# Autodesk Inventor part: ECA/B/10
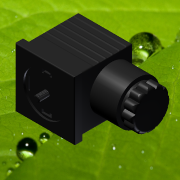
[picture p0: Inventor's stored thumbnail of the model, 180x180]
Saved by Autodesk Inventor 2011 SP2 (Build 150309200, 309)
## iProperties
Category: PARTsolutions
Created: 2013-04
Part Number: ECA/B/10
Catalog Web Link: www.cadenas.de
Description: EC - Electric connectors
Document SubType Name: Modeling
Designer: PARTsolutions
Material: Пластмасса ABS
Mass: 32.0166 g
Surface Area: 73.2471 cm^2
Volume: 30.2044 cm^3
Density: 1.06 g/cm^3
NB: ECA/B/10
NN: EC
NT: Electric connectors
NBSYN: $TIPO.$CT./$CO./$SR.
LINA: ECA/B/10
TIPO: EC
CT: A
CO: B
SR: 10
COX: 'B','B = black','A','A = grey'
VER: 1
KT: DUMMY
CreationOption_UseAsmMates: false
SUPPLIER: Duplomatic
ARTICLENO: ECA/B/10
BOMINFO: ECA/B/10
CREATOR: CADENAS GmbH
PSOL_IDENT_0: {$CADENAS_DATA\23d-libs\duplomatic\04_solenoid_operated_valves\49000\ec.prj},159 {VTYP=3D},{NB=ECA/B
PSOL_IDENT_1: /10},{LINA=ECA/B/10},{NN=EC},{DATE=03.08.2011 09:28:10},{GEOMDATE=03.08.2011 00:00:00},{VERSION=},{L
PSOL_IDENT_2: INEID=10},{LINESUBID=-1},{WBVAR=CT,CO}  {NB=ECA/B/10},{LINA=ECA/B/10},{KT=DUMMY},{TIPO=EC},{CT=A},{C
PSOL_IDENT_3: O=B},{SR=10},{COX= 'B','B = black','A','A = grey' },{VER=1}
Title: ECA/B/10
Author: Cadenas PARTsolutions
Comments: Electric connectors
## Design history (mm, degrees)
sketch "Sketch_3"
  geometry: L1 (11.5, 13.5)-(-11.5, 13.5); L2 (-13.5, 11.5)-(-13.5, -11.5); L3 (-11.5, -13.5)-(11.5, -13.5); L4 (13.5, -11.5)-(13.5, 11.5); A1 r 2 centre (11.5, 11.5) between (13.5, 11.5) and (11.5, 13.5); A2 r 2 centre (-11.5, 11.5) between (-11.5, 13.5) and (-13.5, 11.5); A3 r 2 centre (-11.5, -11.5) between (-13.5, -11.5) and (-11.5, -13.5); A4 r 2 centre (11.5, -11.5) between (11.5, -13.5) and (13.5, -11.5)
  constraints: 8 end point, 8 point on circle, 4 centre point
extrude "Extrusion1" join sketch "Sketch_3" distance "d0" = 4.99; taper "d1" = 0 deg
sketch "Sketch_5"
  geometry: L1 (-13.05, -13.75)-(13.05, -13.75); L2 (13.75, -13.05)-(13.75, 13.05); L3 (13.05, 13.75)-(-13.05, 13.75); L4 (-13.75, 13.05)-(-13.75, -13.05); A1 r 0.7 centre (-13.05, -13.05) between (-13.75, -13.05) and (-13.05, -13.75); A2 r 0.7 centre (13.05, -13.05) between (13.05, -13.75) and (13.75, -13.05); A3 r 0.7 centre (13.05, 13.05) between (13.75, 13.05) and (13.05, 13.75); A4 r 0.7 centre (-13.05, 13.05) between (-13.05, 13.75) and (-13.75, 13.05)
  constraints: 8 end point, 8 point on circle, 4 centre point
extrude "Extrusion2" join sketch "Sketch_5" distance "d2" = 30; taper "d3" = 0 deg
sketch "Sketch_32"
  geometry: L1 (-18.75, 32)-(-18.75, 17); L2 (-18.75, 17)-(-13.75, 17); L3 (-13.75, 17)-(-13.75, 26); L4 (-12.75, 27)-(12.75, 27); L5 (13.75, 26)-(13.75, 17); L6 (13.75, 17)-(18.75, 17); L7 (18.75, 17)-(18.75, 32); L8 (18.75, 32)-(-18.75, 32); A1 r 1 centre (-12.75, 26) between (-12.75, 27) and (-13.75, 26); A2 r 1 centre (12.75, 26) between (13.75, 26) and (12.75, 27)
  constraints: 16 end point, 4 point on circle, 2 centre point
extrude "Extrusion3" cut sketch "Sketch_32" stored distance "d4" = 60; taper "d5" = 0 deg
sketch "Sketch_33"
  geometry: L1 (32, 18.75)-(17, 18.75); L2 (17, 18.75)-(17, 13.75); L3 (17, 13.75)-(26, 13.75); L4 (27, 12.75)-(27, -12.75); L5 (26, -13.75)-(17, -13.75); L6 (17, -13.75)-(17, -18.75); L7 (17, -18.75)-(32, -18.75); L8 (32, -18.75)-(32, 18.75); A1 r 1 centre (26, 12.75) between (27, 12.75) and (26, 13.75); A2 r 1 centre (26, -12.75) between (26, -13.75) and (27, -12.75)
  constraints: 16 end point, 4 point on circle, 2 centre point
extrude "Extrusion4" cut sketch "Sketch_33" stored distance "d6" = 60; taper "d7" = 0 deg
sketch "Sketch_1"
  geometry: L1 (27.25, 16)-(0, 16); L2 (0, 16)-(0, 27); L3 (0, 27)-(27.25, 27); L4 (27.25, 27)-(27.25, 16); L5 (27.25, 16)-(0, 16)
  constraints: 10 end point
revolve "Revolution1" sketch "Sketch_1" stored, may be unused: angle "d8" = 360 deg
sketch "Sketch_2"
  geometry: L1 (34.16, 16)-(27.25, 16); L2 (27.25, 16)-(27.25, 24.95); L3 (27.25, 24.95)-(28.85, 24.95); L4 (28.85, 24.95)-(28.85, 25.95); L5 (28.85, 25.95)-(32.41, 25.95); L6 (34.16, 24.2)-(34.16, 16); L7 (34.16, 16)-(27.25, 16); A1 r 1.75 centre (32.41, 24.2) between (34.16, 24.2) and (32.41, 25.95)
  constraints: 14 end point, 2 point on circle, 1 centre point
revolve "Revolution2" sketch "Sketch_2" stored, may be unused: angle "d9" = 360 deg
sketch "Sketch_4"
  geometry: L1 (-15, 30)-(-15, 0); L2 (-15, 0)-(15, 0); L3 (15, 0)-(15, 30); L4 (15, 30)-(-15, 30); L5 (-8.95, 14.268)-(-8.162, 13.813); L6 (-8.162, 13.813)-(-8.617, 13.025); L7 (-6.885, 10.025)-(-5.975, 10.025); L8 (-5.975, 10.025)-(-5.975, 9.115); L9 (-2.975, 7.383)-(-2.187, 7.838); L10 (-2.187, 7.838)-(-1.732, 7.05); L11 (1.732, 7.05)-(2.187, 7.838); L12 (2.187, 7.838)-(2.975, 7.383); L13 (5.975, 9.115)-(5.975, 10.025); L14 (5.975, 10.025)-(6.885, 10.025); L15 (8.617, 13.025)-(8.162, 13.813); L16 (8.162, 13.813)-(8.95, 14.268); L17 (8.95, 17.732)-(8.162, 18.187); L18 (8.162, 18.187)-(8.617, 18.975); L19 (6.885, 21.975)-(5.975, 21.975); L20 (5.975, 21.975)-(5.975, 22.885); L21 (2.975, 24.617)-(2.187, 24.162); L22 (2.187, 24.162)-(1.732, 24.95); L23 (-1.732, 24.95)-(-2.187, 24.162); L24 (-2.187, 24.162)-(-2.975, 24.617); L25 (-5.975, 22.885)-(-5.975, 21.975); L26 (-5.975, 21.975)-(-6.885, 21.975); L27 (-8.617, 18.975)-(-8.162, 18.187); L28 (-8.162, 18.187)-(-8.95, 17.732); A1 r 2 centre (-7.95, 16) between (-8.95, 17.732) and (-8.95, 14.268); A2 r 2 centre (-6.885, 12.025) between (-8.617, 13.025) and (-6.885, 10.025); A3 r 2 centre (-3.975, 9.115) between (-5.975, 9.115) and (-2.975, 7.383); A4 r 2 centre (0, 8.05) between (-1.732, 7.05) and (1.732, 7.05); A5 r 2 centre (3.975, 9.115) between (2.975, 7.383) and (5.975, 9.115); A6 r 2 centre (6.885, 12.025) between (6.885, 10.025) and (8.617, 13.025); A7 r 2 centre (7.95, 16) between (8.95, 14.268) and (8.95, 17.732); A8 r 2 centre (6.885, 19.975) between (8.617, 18.975) and (6.885, 21.975); A9 r 2 centre (3.975, 22.885) between (5.975, 22.885) and (2.975, 24.617); A10 r 2 centre (0, 23.95) between (1.732, 24.95) and (-1.732, 24.95); A11 r 2 centre (-3.975, 22.885) between (-2.975, 24.617) and (-5.975, 22.885); A12 r 2 centre (-6.885, 19.975) between (-6.885, 21.975) and (-8.617, 18.975)
  constraints: 56 end point, 24 point on circle, 12 centre point
extrude "Extrusion5" cut sketch "Sketch_4" distance "d10" = 10; taper "d11" = 0 deg
sketch "Sketch_6"
  geometry: L1 (0, -8.3)-(0, -2); L2 (0, -2)-(1.5, -2); L3 (1.5, -2)-(1.5, -7.994); L4 (1.5, -7.994)-(1.194, -8.3); L5 (1.194, -8.3)-(0, -8.3); L6 (0, -8.3)-(0, -2)
  constraints: 12 end point
revolve "Revolution3" sketch "Sketch_6" stored, may be unused: angle "d12" = 360 deg
thread "Thread1" dims "d13" = 6.3, "d14" = 0
sketch "Sketch_7"
  geometry: C1 r 3.15 at (0, 0); 1 further point
  constraints: 1 centre point
extrude "Extrusion6" cut sketch "Sketch_7" distance "d15" = 4; taper "d16" = 0 deg
sketch "Sketch_8"
  geometry: L1 (0, 23.5)-(0, 26); L2 (0, 26)-(1, 26); L3 (2.5, 24.5)-(2.5, 23.987); L4 (2.5, 23.987)-(3, 23.987); L5 (3, 23.987)-(3, 23.5); L6 (3, 23.5)-(0, 23.5); L7 (0, 23.5)-(0, 26); A1 r 1.5 centre (1, 24.5) between (2.5, 24.5) and (1, 26)
  constraints: 14 end point, 2 point on circle, 1 centre point
revolve "Revolution4" sketch "Sketch_8" stored, may be unused: angle "d17" = 360 deg
sketch "Sketch_9"
  geometry: L1 (-1.5, 0.3)-(-1.5, -0.3); L2 (-1.5, -0.3)-(-0.3, -0.3); L3 (-0.3, -0.3)-(-0.3, -1.5); L4 (-0.3, -1.5)-(0.3, -1.5); L5 (0.3, -1.5)-(0.3, -0.3); L6 (0.3, -0.3)-(1.5, -0.3); L7 (1.5, -0.3)-(1.5, 0.3); L8 (1.5, 0.3)-(0.3, 0.3); L9 (0.3, 0.3)-(0.3, 1.5); L10 (0.3, 1.5)-(-0.3, 1.5); L11 (-0.3, 1.5)-(-0.3, 0.3); L12 (-0.3, 0.3)-(-1.5, 0.3)
  constraints: 24 end point
extrude "Extrusion7" cut sketch "Sketch_9" distance "d18" = 2; taper "d19" = 0 deg
sketch "Sketch_10"
  geometry: L1 (-9.3, 3.25)-(-9.3, -3.25); L2 (-9.3, -3.25)-(-8.5, -3.25); L3 (-8.5, -3.25)-(-8.5, 3.25); L4 (-8.5, 3.25)-(-9.3, 3.25)
  constraints: 8 end point
extrude "Extrusion8" cut sketch "Sketch_10" distance "d20" = 12; taper "d21" = 0 deg
sketch "Sketch_11"
  geometry: L1 (-2.5, 9.8)-(-2.5, 7.9); L2 (-2.5, 7.9)-(-1.5, 7.9); L3 (-1.5, 7.9)-(-1.5, 8.8); L4 (-1.5, 8.8)-(1.5, 8.8); L5 (1.5, 8.8)-(1.5, 7.9); L6 (1.5, 7.9)-(2.5, 7.9); L7 (2.5, 7.9)-(2.5, 9.8); L8 (2.5, 9.8)-(-2.5, 9.8)
  constraints: 16 end point
extrude "Extrusion9" cut sketch "Sketch_11" distance "d22" = 10; taper "d23" = 0 deg
sketch "Sketch_12"
  geometry: L1 (-2.5, -9.8)-(2.5, -9.8); L2 (2.5, -9.8)-(2.5, -7.9); L3 (2.5, -7.9)-(1.5, -7.9); L4 (1.5, -7.9)-(1.5, -8.8); L5 (1.5, -8.8)-(-1.5, -8.8); L6 (-1.5, -8.8)-(-1.5, -7.9); L7 (-1.5, -7.9)-(-2.5, -7.9); L8 (-2.5, -7.9)-(-2.5, -9.8)
  constraints: 16 end point
extrude "Extrusion10" cut sketch "Sketch_12" distance "d24" = 10; taper "d25" = 0 deg
sketch "Sketch_14"
  geometry: L1 (15, -15)-(15, 15); L2 (15, 15)-(-15, 15); L3 (-15, 15)-(-15, -15); L4 (-15, -15)-(15, -15); C1 r 10.9 at (0, 0); 1 further point
  constraints: 8 end point, 1 centre point
extrude "Extrusion11" join sketch "Sketch_14" distance "d26" = 4; taper "d27" = 0 deg
sketch "Sketch_30"
  geometry: L1 (-20, 0)-(-20, -14); L2 (-20, -14)-(20, -14); L3 (20, -14)-(20, 0); L4 (20, 0)-(15, 0); L5 (15, 0)-(15, -3.5); L6 (14.5, -4)-(10, -4); L7 (10, -4)-(10, -9); L8 (10, -9)-(-10, -9); L9 (-10, -9)-(-10, -4); L10 (-10, -4)-(-14.5, -4); L11 (-15, -3.5)-(-15, 0); L12 (-15, 0)-(-20, 0); A1 r 0.5 centre (14.5, -3.5) between (14.5, -4) and (15, -3.5); A2 r 0.5 centre (-14.5, -3.5) between (-15, -3.5) and (-14.5, -4)
  constraints: 24 end point, 4 point on circle, 2 centre point
extrude "Extrusion12" cut sketch "Sketch_30" stored distance "d28" = 60; taper "d29" = 0 deg
sketch "Sketch_31"
  geometry: L1 (0, 20)-(-14, 20); L2 (-14, 20)-(-14, -20); L3 (-14, -20)-(0, -20); L4 (0, -20)-(0, -15); L5 (0, -15)-(-3.5, -15); L6 (-4, -14.5)-(-4, -10); L7 (-4, -10)-(-9, -10); L8 (-9, -10)-(-9, 10); L9 (-9, 10)-(-4, 10); L10 (-4, 10)-(-4, 14.5); L11 (-3.5, 15)-(0, 15); L12 (0, 15)-(0, 20); A1 r 0.5 centre (-3.5, -14.5) between (-4, -14.5) and (-3.5, -15); A2 r 0.5 centre (-3.5, 14.5) between (-3.5, 15) and (-4, 14.5)
  constraints: 24 end point, 4 point on circle, 2 centre point
extrude "Extrusion13" cut sketch "Sketch_31" stored distance "d30" = 60; taper "d31" = 0 deg
sketch "Sketch_16"
  geometry: L1 (6.7, 15)-(6.7, 13.75); L2 (6.7, 13.75)-(7.249, 13.55); L3 (7.249, 13.55)-(9.611, 13.55); L4 (9.611, 13.55)-(10.16, 13.75); L5 (10.16, 13.75)-(10.2, 13.75); L6 (10.2, 13.75)-(10.749, 13.55); L7 (10.749, 13.55)-(13.111, 13.55); L8 (13.111, 13.55)-(13.66, 13.75); L9 (13.66, 13.75)-(13.7, 13.75); L10 (13.7, 13.75)-(14.249, 13.55); L11 (14.249, 13.55)-(16.611, 13.55); L12 (16.611, 13.55)-(17.16, 13.75); L13 (17.16, 13.75)-(17.2, 13.75); L14 (17.2, 13.75)-(17.749, 13.55); L15 (17.749, 13.55)-(20.111, 13.55); L16 (20.111, 13.55)-(20.66, 13.75); L17 (20.66, 13.75)-(20.7, 13.75); L18 (20.7, 13.75)-(21.249, 13.55); L19 (21.249, 13.55)-(23.611, 13.55); L20 (23.611, 13.55)-(24.16, 13.75); L21 (24.16, 13.75)-(24.2, 13.75); L22 (24.2, 13.75)-(24.2, 15); L23 (24.2, 15)-(6.7, 15)
  constraints: 46 end point
extrude "Extrusion14" cut sketch "Sketch_16" stored distance "d32" = 40; taper "d33" = 0 deg
sketch "Sketch_18"
  geometry: L1 (7.249, -13.55)-(6.7, -13.75); L2 (6.7, -13.75)-(6.7, -15); L3 (6.7, -15)-(24.2, -15); L4 (24.2, -15)-(24.2, -13.75); L5 (24.2, -13.75)-(24.16, -13.75); L6 (24.16, -13.75)-(23.611, -13.55); L7 (23.611, -13.55)-(21.249, -13.55); L8 (21.249, -13.55)-(20.7, -13.75); L9 (20.7, -13.75)-(20.66, -13.75); L10 (20.66, -13.75)-(20.111, -13.55); L11 (20.111, -13.55)-(17.749, -13.55); L12 (17.749, -13.55)-(17.2, -13.75); L13 (17.2, -13.75)-(17.16, -13.75); L14 (17.16, -13.75)-(16.611, -13.55); L15 (16.611, -13.55)-(14.249, -13.55); L16 (14.249, -13.55)-(13.7, -13.75); L17 (13.7, -13.75)-(13.66, -13.75); L18 (13.66, -13.75)-(13.111, -13.55); L19 (13.111, -13.55)-(10.749, -13.55); L20 (10.749, -13.55)-(10.2, -13.75); L21 (10.2, -13.75)-(10.16, -13.75); L22 (10.16, -13.75)-(9.611, -13.55); L23 (9.611, -13.55)-(7.249, -13.55)
  constraints: 46 end point
extrude "Extrusion15" cut sketch "Sketch_18" stored distance "d34" = 40; taper "d35" = 0 deg
sketch "Sketch_17"
  geometry: L1 (-15, 6.7)-(-13.75, 6.7); L2 (-13.75, 6.7)-(-13.55, 7.249); L3 (-13.55, 7.249)-(-13.55, 9.611); L4 (-13.55, 9.611)-(-13.75, 10.16); L5 (-13.75, 10.16)-(-13.75, 10.2); L6 (-13.75, 10.2)-(-13.55, 10.749); L7 (-13.55, 10.749)-(-13.55, 13.111); L8 (-13.55, 13.111)-(-13.75, 13.66); L9 (-13.75, 13.66)-(-13.75, 13.7); L10 (-13.75, 13.7)-(-13.55, 14.249); L11 (-13.55, 14.249)-(-13.55, 16.611); L12 (-13.55, 16.611)-(-13.75, 17.16); L13 (-13.75, 17.16)-(-13.75, 17.2); L14 (-13.75, 17.2)-(-13.55, 17.749); L15 (-13.55, 17.749)-(-13.55, 20.111); L16 (-13.55, 20.111)-(-13.75, 20.66); L17 (-13.75, 20.66)-(-13.75, 20.7); L18 (-13.75, 20.7)-(-13.55, 21.249); L19 (-13.55, 21.249)-(-13.55, 23.611); L20 (-13.55, 23.611)-(-13.75, 24.16); L21 (-13.75, 24.16)-(-13.75, 24.2); L22 (-13.75, 24.2)-(-15, 24.2); L23 (-15, 24.2)-(-15, 6.7)
  constraints: 46 end point
extrude "Extrusion16" cut sketch "Sketch_17" distance "d36" = 5; taper "d37" = 0 deg
sketch "Sketch_19"
  geometry: L1 (-15, 6.7)-(-13.75, 6.7); L2 (-13.75, 6.7)-(-13.55, 7.249); L3 (-13.55, 7.249)-(-13.55, 9.611); L4 (-13.55, 9.611)-(-13.75, 10.16); L5 (-13.75, 10.16)-(-13.75, 10.2); L6 (-13.75, 10.2)-(-13.55, 10.749); L7 (-13.55, 10.749)-(-13.55, 13.111); L8 (-13.55, 13.111)-(-13.75, 13.66); L9 (-13.75, 13.66)-(-13.75, 13.7); L10 (-13.75, 13.7)-(-13.55, 14.249); L11 (-13.55, 14.249)-(-13.55, 16.611); L12 (-13.55, 16.611)-(-13.75, 17.16); L13 (-13.75, 17.16)-(-13.75, 17.2); L14 (-13.75, 17.2)-(-13.55, 17.749); L15 (-13.55, 17.749)-(-13.55, 20.111); L16 (-13.55, 20.111)-(-13.75, 20.66); L17 (-13.75, 20.66)-(-13.75, 20.7); L18 (-13.75, 20.7)-(-13.55, 21.249); L19 (-13.55, 21.249)-(-13.55, 23.611); L20 (-13.55, 23.611)-(-13.75, 24.16); L21 (-13.75, 24.16)-(-13.75, 24.2); L22 (-13.75, 24.2)-(-15, 24.2); L23 (-15, 24.2)-(-15, 6.7)
  constraints: 46 end point
extrude "Extrusion17" cut sketch "Sketch_19" distance "d38" = 5; taper "d39" = 0 deg
sketch "Sketch_20"
  geometry: L1 (-13.55, 10.421)-(-13.75, 10.421); L2 (-13.75, 10.421)-(-13.75, 12.151); L3 (-13.75, 12.151)-(-13.55, 11.602); L4 (-13.55, 11.602)-(-13.55, 10.421); L5 (-13.55, 10.421)-(-13.75, 10.421)
  constraints: 10 end point
revolve "Revolution5" sketch "Sketch_20" stored, may be unused: angle "d40" = 360 deg
sketch "Sketch_21"
  geometry: L1 (-13.55, 10.421)-(-13.75, 10.421); L2 (-13.75, 10.421)-(-13.75, 12.151); L3 (-13.75, 12.151)-(-13.55, 11.602); L4 (-13.55, 11.602)-(-13.55, 10.421); L5 (-13.55, 10.421)-(-13.75, 10.421)
  constraints: 10 end point
revolve "Revolution6" sketch "Sketch_21" stored, may be unused: angle "d41" = 360 deg
sketch "Sketch_22"
  geometry: L1 (-13.55, 10.421)-(-13.75, 10.421); L2 (-13.75, 10.421)-(-13.75, 12.151); L3 (-13.75, 12.151)-(-13.55, 11.602); L4 (-13.55, 11.602)-(-13.55, 10.421); L5 (-13.55, 10.421)-(-13.75, 10.421)
  constraints: 10 end point
revolve "Revolution7" sketch "Sketch_22" stored, may be unused: angle "d42" = 360 deg
sketch "Sketch_23"
  geometry: L1 (-13.55, 10.421)-(-13.75, 10.421); L2 (-13.75, 10.421)-(-13.75, 12.151); L3 (-13.75, 12.151)-(-13.55, 11.602); L4 (-13.55, 11.602)-(-13.55, 10.421); L5 (-13.55, 10.421)-(-13.75, 10.421)
  constraints: 10 end point
revolve "Revolution8" sketch "Sketch_23" stored, may be unused: angle "d43" = 360 deg
sketch "Sketch_24"
  geometry: L1 (-13.55, 10.421)-(-13.75, 10.421); L2 (-13.75, 10.421)-(-13.75, 12.151); L3 (-13.75, 12.151)-(-13.55, 11.602); L4 (-13.55, 11.602)-(-13.55, 10.421); L5 (-13.55, 10.421)-(-13.75, 10.421)
  constraints: 10 end point
revolve "Revolution9" sketch "Sketch_24" stored, may be unused: angle "d44" = 360 deg
sketch "Sketch_25"
  geometry: L1 (-13.75, -10.421)-(-13.55, -10.421); L2 (-13.55, -10.421)-(-13.55, -11.602); L3 (-13.55, -11.602)-(-13.75, -12.151); L4 (-13.75, -12.151)-(-13.75, -10.421); L5 (-13.75, -10.421)-(-13.55, -10.421)
  constraints: 10 end point
revolve "Revolution10" sketch "Sketch_25" stored, may be unused: angle "d45" = 360 deg
sketch "Sketch_26"
  geometry: L1 (-13.75, -10.421)-(-13.55, -10.421); L2 (-13.55, -10.421)-(-13.55, -11.602); L3 (-13.55, -11.602)-(-13.75, -12.151); L4 (-13.75, -12.151)-(-13.75, -10.421); L5 (-13.75, -10.421)-(-13.55, -10.421)
  constraints: 10 end point
revolve "Revolution11" sketch "Sketch_26" stored, may be unused: angle "d46" = 360 deg
sketch "Sketch_27"
  geometry: L1 (-13.75, -10.421)-(-13.55, -10.421); L2 (-13.55, -10.421)-(-13.55, -11.602); L3 (-13.55, -11.602)-(-13.75, -12.151); L4 (-13.75, -12.151)-(-13.75, -10.421); L5 (-13.75, -10.421)-(-13.55, -10.421)
  constraints: 10 end point
revolve "Revolution12" sketch "Sketch_27" stored, may be unused: angle "d47" = 360 deg
sketch "Sketch_28"
  geometry: L1 (-13.75, -10.421)-(-13.55, -10.421); L2 (-13.55, -10.421)-(-13.55, -11.602); L3 (-13.55, -11.602)-(-13.75, -12.151); L4 (-13.75, -12.151)-(-13.75, -10.421); L5 (-13.75, -10.421)-(-13.55, -10.421)
  constraints: 10 end point
revolve "Revolution13" sketch "Sketch_28" stored, may be unused: angle "d48" = 360 deg
sketch "Sketch_29"
  geometry: L1 (-13.75, -10.421)-(-13.55, -10.421); L2 (-13.55, -10.421)-(-13.55, -11.602); L3 (-13.55, -11.602)-(-13.75, -12.151); L4 (-13.75, -12.151)-(-13.75, -10.421); L5 (-13.75, -10.421)-(-13.55, -10.421)
  constraints: 10 end point
revolve "Revolution14" sketch "Sketch_29" stored, may be unused: angle "d49" = 360 deg
node "IP1_XY"
node "IP1_YZ"
node "IP1_ZX"
node "IP1_X"
node "IP1_Y"
node "IP1_Z"
node "IP1_Center"
node "IP2_XY"
node "IP2_YZ"
node "IP2_ZX"
node "IP2_X"
node "IP2_Y"
node "IP2_Z"
node "IP2_Center"
node "Твердое тело1"
node "Твердые тела"
node "Поверхностные тела"
